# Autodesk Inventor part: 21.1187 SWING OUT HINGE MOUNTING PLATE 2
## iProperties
Created: 2007-07
Part Number: 21.1187 SWING OUT HINGE MOUNTING PLATE 2
Document SubType Name: Modeling
Designer: Andy Moles
Material: Steel
Mass: 12.2113 g
Surface Area: 29.2463 cm^2
Volume: 1.55558 cm^3
Density: 7.85 g/cm^3
Author: Andy Moles
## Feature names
1. Extrusion1
2. Extrusion3
3. Mirror2
